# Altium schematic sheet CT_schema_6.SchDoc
size 226 x 144 mm
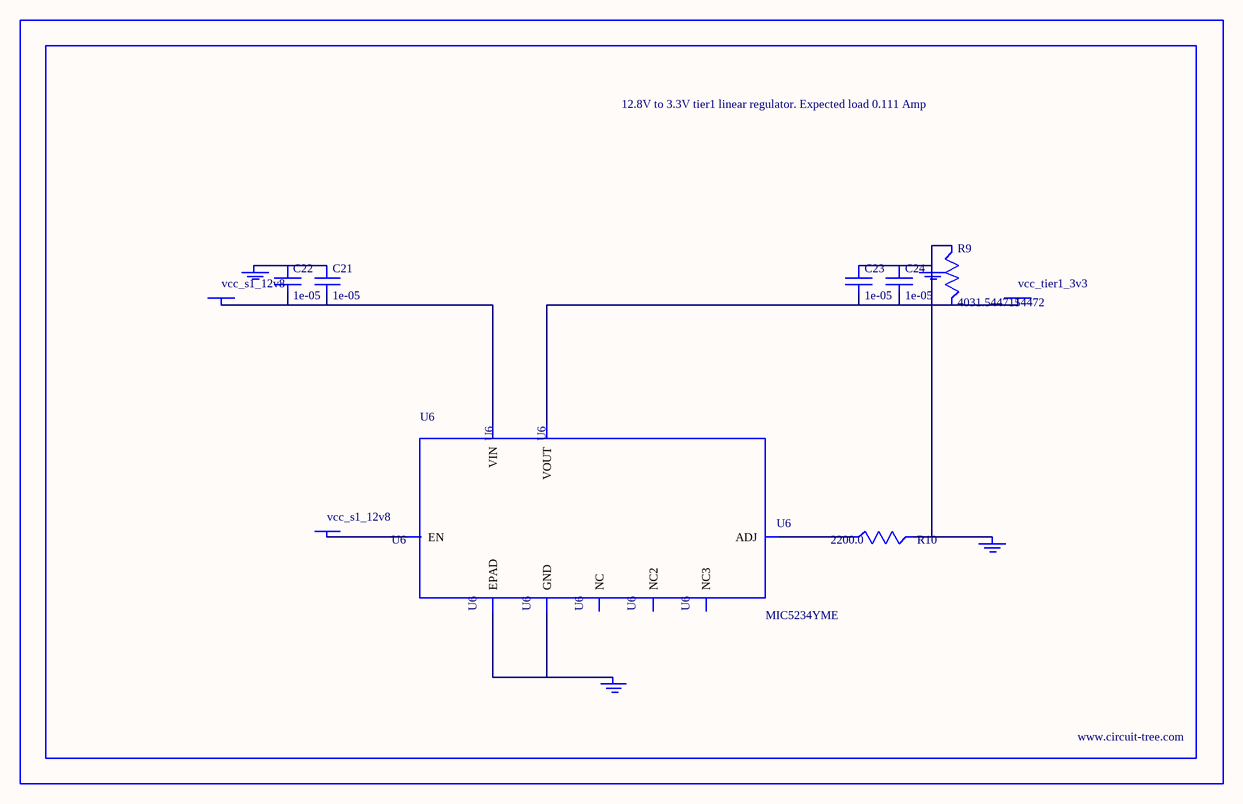
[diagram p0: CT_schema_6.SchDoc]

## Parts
BORDER5  (no value)
C21  1e-05  [C1210]
C22  1e-05  [C1210]
C23  1e-05  [C1210]
C24  1e-05  [C1210]
GND_INSTANCE_5_0  (no value)
GND_INSTANCE_5_1  (no value)
GND_INSTANCE_5_2  (no value)
GND_INSTANCE_5_3  (no value)
POWER_INSTANCE_5_0  vcc_tier1_3v3
POWER_INSTANCE_5_1  vcc_s1_12v8
POWER_INSTANCE_5_2  vcc_s1_12v8
R9  4031.5447154472  [R0603]
R10  2200.0  [R0603]
U6  MIC5234YME  [SOIC-8_EP]

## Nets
NetC21_1: C21.1 C22.1 GND_INSTANCE_5_3.0(GND)
NetC21_2: C21.2 C22.2 POWER_INSTANCE_5_2.0(PWR) U6.8(VIN)
NetC23_1: C23.1 C24.1 GND_INSTANCE_5_0.0(GND) GND_INSTANCE_5_1.0(GND) R9.1 R10.2
NetC23_2: C23.2 C24.2 POWER_INSTANCE_5_0.0(PWR) R9.2 U6.1(VOUT)
NetGND_INSTANCE_5_2_0: GND_INSTANCE_5_2.0(GND) U6.7(GND) U6.EPAD
NetPOWER_INSTANCE_5_1_0: POWER_INSTANCE_5_1.0(PWR) U6.5(EN)
NetR10_1: R10.1 U6.4(ADJ)

Not connected (* = marked no-connect by the designer): U6 2(NC) 3(NC2) 6(NC3)

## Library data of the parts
BORDER5 = BORDER_PAGE5
C21-C24 = C1210C106K5PACTU
GND_INSTANCE_5_0-GND_INSTANCE_5_3 = GND
POWER_INSTANCE_5_0-POWER_INSTANCE_5_2 = PWR
R9 = R9
R10 = RC0603JR-072K2L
